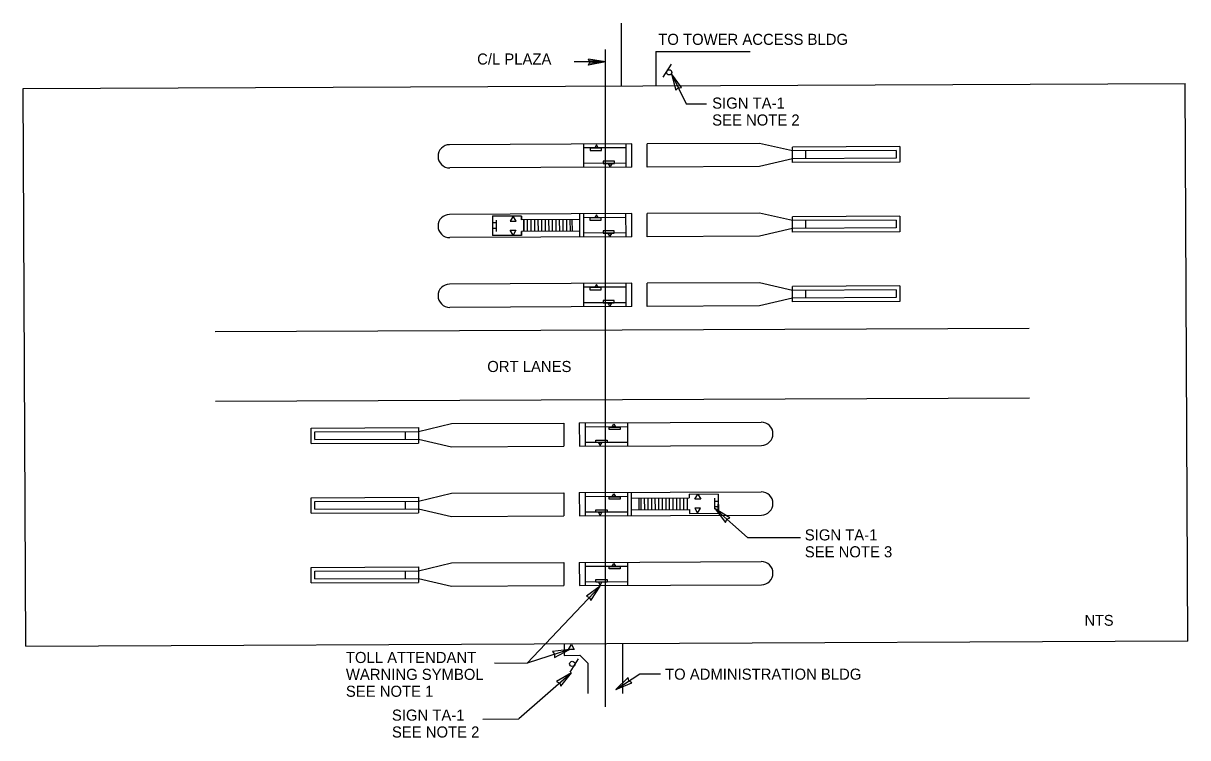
# Model space of a CAD drawing. Extents: x 53068 to 53703, y 9291 to 9710.
# Drawn here: x 53092.3 to 53393, y 9525.4 to 9710 of the extents above; entities that cross this region are included whole.
import ezdxf

# ---------------------------------------------------------------- set-up
doc = ezdxf.new("R2010")
doc.units = 0
for name, color, linetype in [('LeaderLine_dp', 7, 'Continuous'), ('RoadwayMisc', 7, 'Continuous'), ('SignSupport', 7, 'Continuous'), ('TextLabel', 7, 'Continuous')]:
    doc.layers.add(name, color=color, linetype=linetype)

msp = doc.modelspace()

# ---------------------------------------------------------------- linework, layer by layer
at = {"layer": 'LeaderLine_dp'}
for p, q in [((53242.67, 9700.05), (53234.59, 9700.05)), ((53242.67, 9700.05), (53238.29, 9700.74)), ((53238.63, 9699.98), (53238.29, 9700.74)), ((53242.67, 9700.05), (53238.31, 9699.2)), ((53238.31, 9699.2), (53238.63, 9699.98)), ((53242.67, 9700.05), (53238.47, 9700.34)), ((53242.67, 9700.05), (53238.48, 9699.61)), ((53259.69, 9696.96), (53263.48, 9689.16)), ((53259.69, 9696.96), (53260.83, 9692.68)), ((53262.32, 9693.4), (53259.69, 9696.96)), ((53260.83, 9692.68), (53261.45, 9693.35)), ((53261.45, 9693.35), (53262.32, 9693.4)), ((53263.48, 9689.16), (53268.78, 9689.16)), ((53270.97, 9584.53), (53279.39, 9577.19)), ((53270.97, 9584.53), (53273.7, 9581.04)), ((53274.78, 9582.28), (53270.97, 9584.53)), ((53270.97, 9584.53), (53273.7, 9581.04)), ((53274.78, 9582.28), (53270.97, 9584.53)), ((53273.7, 9581.04), (53274, 9581.89)), ((53273.7, 9581.04), (53274, 9581.89)), ((53274, 9581.89), (53274.78, 9582.28)), ((53274, 9581.89), (53274.78, 9582.28)), ((53279.39, 9577.19), (53293.03, 9577.19)), ((53222.44, 9544.71), (53241.34, 9564.61)), ((53241.34, 9564.61), (53237.74, 9562.03)), ((53238.93, 9560.89), (53241.34, 9564.61)), ((53237.74, 9562.03), (53238.57, 9561.69)), ((53238.57, 9561.69), (53238.93, 9560.89)), ((53233.37, 9548.24), (53222.44, 9544.71)), ((53233.37, 9548.24), (53228.98, 9547.7)), ((53233.37, 9548.24), (53228.98, 9547.7)), ((53229.48, 9546.13), (53233.37, 9548.24)), ((53229.48, 9546.13), (53233.37, 9548.24)), ((53214.03, 9544.76), (53222.44, 9544.71)), ((53228.98, 9547.7), (53229.55, 9547)), ((53228.98, 9547.7), (53229.55, 9547)), ((53229.55, 9547), (53229.48, 9546.13)), ((53229.55, 9547), (53229.48, 9546.13)), ((53233.87, 9542.23), (53220.29, 9530.3)), ((53233.87, 9542.23), (53230.05, 9539.99)), ((53231.14, 9538.75), (53233.87, 9542.23)), ((53245.38, 9537.89), (53251.55, 9541.98)), ((53251.55, 9541.98), (53256.85, 9541.98)), ((53230.05, 9539.99), (53230.85, 9539.58)), ((53230.85, 9539.58), (53231.14, 9538.75)), ((53248.56, 9540.97), (53245.38, 9537.89)), ((53248.56, 9540.97), (53245.38, 9537.89)), ((53245.38, 9537.89), (53249.47, 9539.59)), ((53245.38, 9537.89), (53249.47, 9539.59)), ((53248.73, 9540.11), (53248.56, 9540.97)), ((53248.73, 9540.11), (53248.56, 9540.97)), ((53249.47, 9539.59), (53248.73, 9540.11)), ((53249.47, 9539.59), (53248.73, 9540.11)), ((53211, 9530.23), (53220.29, 9530.3))]:
    msp.add_line(p, q, dxfattribs=at)
at = {"layer": 'RoadwayMisc'}
for p, q in [((53246.72, 9710), (53246.72, 9693.82)), ((53242.67, 9533.39), (53242.67, 9703.23)), ((53255.7, 9702.7), (53255.7, 9693.86)), ((53255.7, 9702.7), (53280.02, 9702.7)), ((53092.32, 9693.14), (53392.41, 9694.46)), ((53092.95, 9549.11), (53092.32, 9693.14)), ((53393.04, 9550.42), (53392.41, 9694.45)), ((53249.44, 9678.84), (53202.42, 9678.63)), ((53237.02, 9678.79), (53237.04, 9672.79)), ((53247.94, 9677.83), (53237.02, 9677.8)), ((53241.62, 9677.77), (53238.7, 9677.77)), ((53238.7, 9677.77), (53238.7, 9677.14)), ((53238.7, 9677.14), (53241.62, 9677.14)), ((53240.38, 9678.57), (53239.95, 9677.83)), ((53239.95, 9677.83), (53240.81, 9677.83)), ((53240.81, 9677.83), (53240.38, 9678.57)), ((53241.62, 9677.14), (53241.62, 9677.77)), ((53247.94, 9678.83), (53247.96, 9672.83)), ((53249.51, 9672.84), (53249.44, 9678.84)), ((53282.44, 9678.98), (53253.44, 9678.86)), ((53253.46, 9672.86), (53253.44, 9678.86)), ((53290.96, 9677.02), (53282.44, 9678.98)), ((53318.71, 9678.15), (53290.95, 9678.02)), ((53290.97, 9674.02), (53290.95, 9678.02)), ((53317.71, 9677.14), (53290.96, 9677.02)), ((53317.71, 9677.14), (53317.72, 9675.14)), ((53318.71, 9678.15), (53318.73, 9674.14)), ((53245.02, 9674.39), (53242.1, 9674.39)), ((53242.1, 9674.39), (53242.1, 9673.76)), ((53245.02, 9673.76), (53245.02, 9674.39)), ((53290.96, 9675.02), (53282.47, 9672.98)), ((53317.72, 9675.14), (53290.96, 9675.02)), ((53318.73, 9674.14), (53290.97, 9674.02)), ((53294.45, 9675.04), (53294.44, 9677.04)), ((53249.46, 9672.84), (53202.45, 9672.63)), ((53247.95, 9673.83), (53237.04, 9673.79)), ((53242.1, 9673.76), (53245.02, 9673.76)), ((53243.89, 9672.99), (53243.46, 9673.73)), ((53243.46, 9673.73), (53244.32, 9673.73)), ((53244.32, 9673.73), (53243.89, 9672.99)), ((53282.47, 9672.98), (53253.46, 9672.86)), ((53249.44, 9660.83), (53202.42, 9660.62)), ((53213.49, 9660.26), (53213.47, 9655.25)), ((53220.97, 9660.21), (53213.47, 9660.18)), ((53213.47, 9660.18), (53213.49, 9655.17)), ((53218.84, 9660.18), (53218.09, 9658.88)), ((53219.59, 9658.88), (53218.84, 9660.18)), ((53220.97, 9660.21), (53220.97, 9659.19)), ((53220.97, 9659.21), (53220.97, 9660.21)), ((53235.97, 9659.27), (53220.97, 9659.21)), ((53221.55, 9659.21), (53221.57, 9656.21)), ((53221.57, 9656.21), (53221.55, 9659.21)), ((53222.47, 9659.22), (53222.49, 9656.21)), ((53223.39, 9659.22), (53223.41, 9656.22)), ((53224.31, 9659.22), (53224.33, 9656.22)), ((53225.23, 9659.23), (53225.25, 9656.22)), ((53226.15, 9659.23), (53226.17, 9656.23)), ((53227.07, 9659.24), (53227.09, 9656.23)), ((53227.99, 9659.24), (53228.01, 9656.24)), ((53228.91, 9659.24), (53228.93, 9656.24)), ((53229.83, 9659.25), (53229.85, 9656.24)), ((53230.75, 9659.25), (53230.77, 9656.25)), ((53231.67, 9659.25), (53231.69, 9656.25)), ((53232.59, 9659.26), (53232.61, 9656.26)), ((53233.51, 9659.26), (53233.53, 9656.26)), ((53234.01, 9659.26), (53234.03, 9656.26)), ((53235.96, 9660.77), (53235.99, 9654.77)), ((53236.96, 9660.78), (53236.99, 9654.78)), ((53247.89, 9659.83), (53236.97, 9659.78)), ((53241.56, 9659.76), (53238.65, 9659.76)), ((53238.65, 9659.76), (53238.65, 9659.14)), ((53238.65, 9659.14), (53241.56, 9659.14)), ((53240.33, 9660.56), (53239.9, 9659.82)), ((53239.9, 9659.82), (53240.75, 9659.82)), ((53240.75, 9659.82), (53240.33, 9660.56)), ((53241.56, 9659.14), (53241.56, 9659.76)), ((53247.88, 9660.83), (53247.91, 9654.83)), ((53249.46, 9654.83), (53249.44, 9660.83)), ((53282.44, 9660.98), (53253.44, 9660.85)), ((53253.46, 9654.85), (53253.44, 9660.85)), ((53290.96, 9659.02), (53282.44, 9660.98)), ((53318.71, 9660.14), (53290.95, 9660.02)), ((53290.97, 9656.02), (53290.95, 9660.02)), ((53317.71, 9659.13), (53290.96, 9659.02)), ((53294.45, 9657.03), (53294.44, 9659.03)), ((53317.71, 9659.13), (53317.72, 9657.14)), ((53318.71, 9660.14), (53318.73, 9656.14)), ((53218.8, 9655.23), (53218.05, 9656.52)), ((53218.05, 9656.52), (53219.55, 9656.52)), ((53218.09, 9658.88), (53219.59, 9658.88)), ((53219.55, 9656.52), (53218.8, 9655.23)), ((53235.99, 9656.27), (53220.99, 9656.21)), ((53220.99, 9656.2), (53220.99, 9655.21)), ((53220.99, 9655.2), (53220.99, 9656.2)), ((53244.96, 9656.38), (53242.04, 9656.38)), ((53242.04, 9656.38), (53242.04, 9655.76)), ((53244.96, 9655.76), (53244.96, 9656.38)), ((53290.96, 9657.02), (53282.47, 9654.98)), ((53317.72, 9657.14), (53290.96, 9657.02)), ((53318.73, 9656.14), (53290.97, 9656.02)), ((53249.46, 9654.83), (53202.45, 9654.62)), ((53220.99, 9655.21), (53213.49, 9655.17)), ((53247.91, 9655.83), (53236.99, 9655.78)), ((53242.04, 9655.76), (53244.96, 9655.76)), ((53243.83, 9654.98), (53243.41, 9655.72)), ((53243.41, 9655.72), (53244.26, 9655.72)), ((53244.26, 9655.72), (53243.83, 9654.98)), ((53282.47, 9654.98), (53253.46, 9654.85)), ((53249.44, 9642.83), (53202.42, 9642.62)), ((53237.02, 9642.78), (53237.04, 9636.78)), ((53247.94, 9641.82), (53237.02, 9641.79)), ((53241.56, 9641.76), (53238.65, 9641.76)), ((53238.65, 9641.76), (53238.65, 9641.13)), ((53238.65, 9641.13), (53241.56, 9641.13)), ((53240.33, 9642.56), (53239.9, 9641.82)), ((53239.9, 9641.82), (53240.75, 9641.82)), ((53240.75, 9641.82), (53240.33, 9642.56)), ((53241.56, 9641.13), (53241.56, 9641.76)), ((53247.94, 9642.82), (53247.96, 9636.82)), ((53249.46, 9636.83), (53249.44, 9642.83)), ((53282.44, 9642.97), (53253.44, 9642.84)), ((53253.46, 9636.84), (53253.44, 9642.84)), ((53290.96, 9641.01), (53282.44, 9642.97)), ((53318.71, 9642.14), (53290.95, 9642.01)), ((53290.97, 9638.01), (53290.95, 9642.01)), ((53317.71, 9641.13), (53290.96, 9641.01)), ((53294.45, 9639.03), (53294.44, 9641.03)), ((53317.71, 9641.13), (53317.72, 9639.13)), ((53318.71, 9642.14), (53318.73, 9638.13)), ((53244.96, 9638.38), (53242.04, 9638.38)), ((53242.04, 9638.38), (53242.04, 9637.75)), ((53244.96, 9637.75), (53244.96, 9638.38)), ((53290.96, 9639.01), (53282.47, 9636.97)), ((53317.72, 9639.13), (53290.96, 9639.01)), ((53318.73, 9638.13), (53290.97, 9638.01)), ((53249.46, 9636.83), (53202.45, 9636.62)), ((53247.95, 9637.82), (53237.04, 9637.78)), ((53242.04, 9637.75), (53244.96, 9637.75)), ((53243.83, 9636.98), (53243.41, 9637.72)), ((53243.41, 9637.72), (53244.26, 9637.72)), ((53244.26, 9637.72), (53243.83, 9636.98)), ((53282.47, 9636.97), (53253.46, 9636.84)), ((53141.84, 9630.35), (53352.08, 9631.28)), ((53141.92, 9612.35), (53352.16, 9613.28)), ((53166.64, 9605.45), (53194.39, 9605.57)), ((53166.66, 9601.45), (53166.64, 9605.45)), ((53194.39, 9605.57), (53194.41, 9601.57)), ((53194.4, 9604.57), (53202.89, 9606.61)), ((53202.89, 9606.61), (53231.9, 9606.74)), ((53231.9, 9606.74), (53231.93, 9600.74)), ((53235.9, 9606.76), (53282.92, 9606.97)), ((53235.9, 9606.76), (53235.93, 9600.76)), ((53237.4, 9606.76), (53237.43, 9600.76)), ((53237.4, 9605.77), (53248.32, 9605.81)), ((53243.59, 9605.05), (53243.59, 9605.67)), ((53243.59, 9605.67), (53246.51, 9605.67)), ((53246.51, 9605.05), (53243.59, 9605.05)), ((53244.4, 9605.74), (53244.83, 9606.48)), ((53245.25, 9605.74), (53244.4, 9605.74)), ((53244.83, 9606.48), (53245.25, 9605.74)), ((53246.51, 9605.67), (53246.51, 9605.05)), ((53248.32, 9606.81), (53248.35, 9600.81)), ((53167.64, 9604.45), (53194.4, 9604.57)), ((53167.65, 9602.46), (53167.64, 9604.45)), ((53167.65, 9602.46), (53194.41, 9602.57)), ((53190.92, 9604.56), (53190.93, 9602.56)), ((53194.41, 9602.57), (53202.92, 9600.61)), ((53240.19, 9601.67), (53240.19, 9602.3)), ((53240.19, 9602.3), (53243.11, 9602.3)), ((53243.11, 9602.3), (53243.11, 9601.67)), ((53166.66, 9601.45), (53194.41, 9601.57)), ((53202.92, 9600.61), (53231.93, 9600.74)), ((53235.93, 9600.76), (53282.95, 9600.96)), ((53237.42, 9601.76), (53248.34, 9601.81)), ((53243.11, 9601.67), (53240.19, 9601.67)), ((53241.75, 9601.64), (53240.89, 9601.64)), ((53240.89, 9601.64), (53241.32, 9600.9)), ((53241.32, 9600.9), (53241.75, 9601.64)), ((53166.64, 9587.44), (53194.39, 9587.57)), ((53166.66, 9583.44), (53166.64, 9587.44)), ((53194.39, 9587.57), (53194.41, 9583.57)), ((53194.4, 9586.57), (53202.89, 9588.6)), ((53202.89, 9588.6), (53231.9, 9588.73)), ((53231.9, 9588.73), (53231.93, 9582.73)), ((53235.9, 9588.75), (53282.92, 9588.96)), ((53235.9, 9588.75), (53235.93, 9582.75)), ((53237.4, 9588.76), (53237.43, 9582.76)), ((53237.4, 9587.76), (53248.32, 9587.81)), ((53243.59, 9587.04), (53243.59, 9587.67)), ((53243.59, 9587.67), (53246.51, 9587.67)), ((53246.51, 9587.04), (53243.59, 9587.04)), ((53244.4, 9587.73), (53244.83, 9588.47)), ((53245.25, 9587.73), (53244.4, 9587.73)), ((53244.83, 9588.47), (53245.25, 9587.73)), ((53246.51, 9587.67), (53246.51, 9587.04)), ((53248.32, 9588.81), (53248.35, 9582.81)), ((53249.32, 9588.81), (53249.34, 9582.81)), ((53249.32, 9587.31), (53264.32, 9587.38)), ((53251.28, 9587.32), (53251.3, 9584.32)), ((53251.78, 9587.32), (53251.8, 9584.32)), ((53252.7, 9587.33), (53252.72, 9584.32)), ((53253.62, 9587.33), (53253.64, 9584.33)), ((53254.54, 9587.33), (53254.56, 9584.33)), ((53255.46, 9587.34), (53255.48, 9584.34)), ((53256.38, 9587.34), (53256.4, 9584.34)), ((53257.3, 9587.35), (53257.32, 9584.34)), ((53258.22, 9587.35), (53258.24, 9584.35)), ((53259.14, 9587.36), (53259.16, 9584.35)), ((53260.06, 9587.36), (53260.08, 9584.36)), ((53260.98, 9587.36), (53261, 9584.36)), ((53261.9, 9587.37), (53261.92, 9584.37)), ((53262.82, 9587.37), (53262.84, 9584.37)), ((53263.74, 9587.38), (53263.76, 9584.37)), ((53264.32, 9588.38), (53271.82, 9588.41)), ((53264.32, 9588.38), (53264.32, 9587.38)), ((53265.76, 9587.06), (53266.51, 9588.36)), ((53267.26, 9587.06), (53265.76, 9587.06)), ((53266.51, 9588.36), (53267.26, 9587.06)), ((53271.82, 9583.33), (53271.84, 9588.33)), ((53271.82, 9588.28), (53271.84, 9583.28)), ((53167.64, 9586.45), (53194.4, 9586.57)), ((53167.65, 9584.45), (53167.64, 9586.45)), ((53167.65, 9584.45), (53194.41, 9584.57)), ((53190.92, 9586.55), (53190.93, 9584.55)), ((53194.41, 9584.57), (53202.92, 9582.6)), ((53240.19, 9583.67), (53240.19, 9584.29)), ((53240.19, 9584.29), (53243.11, 9584.29)), ((53243.11, 9584.29), (53243.11, 9583.67)), ((53249.34, 9584.31), (53264.34, 9584.38)), ((53264.34, 9584.37), (53264.34, 9583.38)), ((53267.22, 9584.71), (53265.72, 9584.71)), ((53265.72, 9584.71), (53266.47, 9583.41)), ((53266.47, 9583.41), (53267.22, 9584.71)), ((53166.66, 9583.44), (53194.41, 9583.57)), ((53202.92, 9582.6), (53231.93, 9582.73)), ((53235.93, 9582.75), (53282.95, 9582.96)), ((53237.42, 9583.76), (53248.34, 9583.81)), ((53243.11, 9583.67), (53240.19, 9583.67)), ((53241.75, 9583.63), (53240.89, 9583.63)), ((53240.89, 9583.63), (53241.32, 9582.89)), ((53241.32, 9582.89), (53241.75, 9583.63)), ((53264.34, 9583.38), (53271.84, 9583.41)), ((53166.64, 9569.44), (53194.39, 9569.56)), ((53166.66, 9565.44), (53166.64, 9569.44)), ((53194.39, 9569.56), (53194.41, 9565.56)), ((53194.4, 9568.56), (53202.89, 9570.6)), ((53202.89, 9570.6), (53231.9, 9570.73)), ((53231.9, 9570.73), (53231.93, 9564.73)), ((53235.9, 9570.75), (53282.92, 9570.96)), ((53235.9, 9570.75), (53235.93, 9564.75)), ((53237.4, 9570.75), (53237.43, 9564.75)), ((53237.4, 9569.76), (53248.32, 9569.8)), ((53243.59, 9569.04), (53243.59, 9569.66)), ((53243.59, 9569.66), (53246.51, 9569.66)), ((53246.51, 9569.04), (53243.59, 9569.04)), ((53244.4, 9569.73), (53244.83, 9570.47)), ((53245.25, 9569.73), (53244.4, 9569.73)), ((53244.83, 9570.47), (53245.25, 9569.73)), ((53246.51, 9569.66), (53246.51, 9569.04)), ((53248.32, 9570.8), (53248.35, 9564.8)), ((53167.64, 9568.44), (53194.4, 9568.56)), ((53167.65, 9566.45), (53167.64, 9568.44)), ((53167.65, 9566.45), (53194.41, 9566.56)), ((53190.92, 9568.55), (53190.93, 9566.55)), ((53194.41, 9566.56), (53202.92, 9564.6)), ((53237.42, 9565.75), (53248.34, 9565.8)), ((53240.19, 9565.66), (53240.19, 9566.29)), ((53240.19, 9566.29), (53243.11, 9566.29)), ((53243.11, 9566.29), (53243.11, 9565.66)), ((53166.66, 9565.44), (53194.41, 9565.56)), ((53202.92, 9564.6), (53231.93, 9564.73)), ((53235.93, 9564.75), (53282.95, 9564.95)), ((53243.11, 9565.66), (53240.19, 9565.66)), ((53241.75, 9565.63), (53240.89, 9565.63)), ((53240.89, 9565.63), (53241.32, 9564.89)), ((53241.32, 9564.89), (53241.75, 9565.63)), ((53092.95, 9549.11), (53393.04, 9550.43)), ((53231.99, 9549.72), (53232.01, 9546.72)), ((53233.11, 9548.24), (53233.86, 9549.54)), ((53234.61, 9548.24), (53233.11, 9548.24)), ((53233.86, 9549.54), (53234.61, 9548.24)), ((53247.17, 9536.91), (53247.17, 9549.79)), ((53232.01, 9546.72), (53236.01, 9546.74)), ((53238.17, 9544.58), (53236.01, 9546.74)), ((53238.17, 9536.91), (53238.17, 9544.58))]:
    msp.add_line(p, q, dxfattribs=at)
for centre, start, end in [((53202.43, 9675.63), 90.2483, 270.2483), ((53202.43, 9657.62), 90.2483, 270.2483), ((53202.43, 9639.62), 90.2483, 270.2483), ((53282.93, 9603.96), 270.2769, 90.2769), ((53282.93, 9585.96), 270.2769, 90.2769), ((53282.93, 9567.95), 270.2769, 90.2769)]:
    msp.add_arc(centre, 3, start, end, dxfattribs=at)
at = {"layer": 'SignSupport'}
for p, q in [((53259.65, 9699.47), (53257.49, 9696.05)), ((53214.42, 9659.11), (53214.41, 9656.22)), ((53214.42, 9658.42), (53213.45, 9658.42)), ((53214.41, 9657.02), (53213.48, 9657.02)), ((53270.89, 9584.47), (53270.9, 9587.36)), ((53270.89, 9585.17), (53271.86, 9585.16)), ((53270.9, 9586.57), (53271.83, 9586.56)), ((53233.57, 9542.36), (53235.73, 9545.78))]:
    msp.add_line(p, q, dxfattribs=at)
for centre in [(53259.12, 9697.32), (53234.1, 9544.51)]:
    msp.add_circle(centre, 0.675, dxfattribs=at)

# ---------------------------------------------------------------- texts
at = {"layer": 'TextLabel'}
for s, height, p in [('TO TOWER ACCESS BLDG', 2.8669, (53256.31, 9704.42)), ('C/L PLAZA', 2.867, (53209.53, 9699.33)), ('SIGN TA-1', 2.867, (53270.23, 9687.95)), ('SEE NOTE 2', 2.867, (53270.23, 9683.58)), ('ORT LANES', 2.867, (53212.15, 9619.91)), ('SIGN TA-1', 2.867, (53294.15, 9576.41)), ('SEE NOTE 3', 2.867, (53294.15, 9572.04)), ('NTS', 2.8, (53366.4, 9554.37)), ('TOLL ATTENDANT', 2.8669, (53175.64, 9544.74)), ('WARNING SYMBOL', 2.8669, (53175.64, 9540.38)), ('TO ADMINISTRATION BLDG', 2.8669, (53258.06, 9540.43)), ('SEE NOTE 1', 2.867, (53175.64, 9536.01)), ('SIGN TA-1', 2.867, (53187.53, 9529.85)), ('SEE NOTE 2', 2.867, (53187.53, 9525.49))]:
    msp.add_text(s, height=height, dxfattribs=at).set_placement(p)

doc.saveas('drawing.dxf')
